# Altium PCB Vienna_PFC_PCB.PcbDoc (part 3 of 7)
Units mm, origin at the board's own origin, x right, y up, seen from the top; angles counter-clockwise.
Board outline 447.04 x 302.51 mm, 6 copper layers (Top Layer, Signal Layer 1, Signal Layer 2, Signal Layer 3, Signal Layer 4, Bottom Layer), stack 1.231 mm thick; 630 components, 255 nets, 1656 pads, 941 vias.
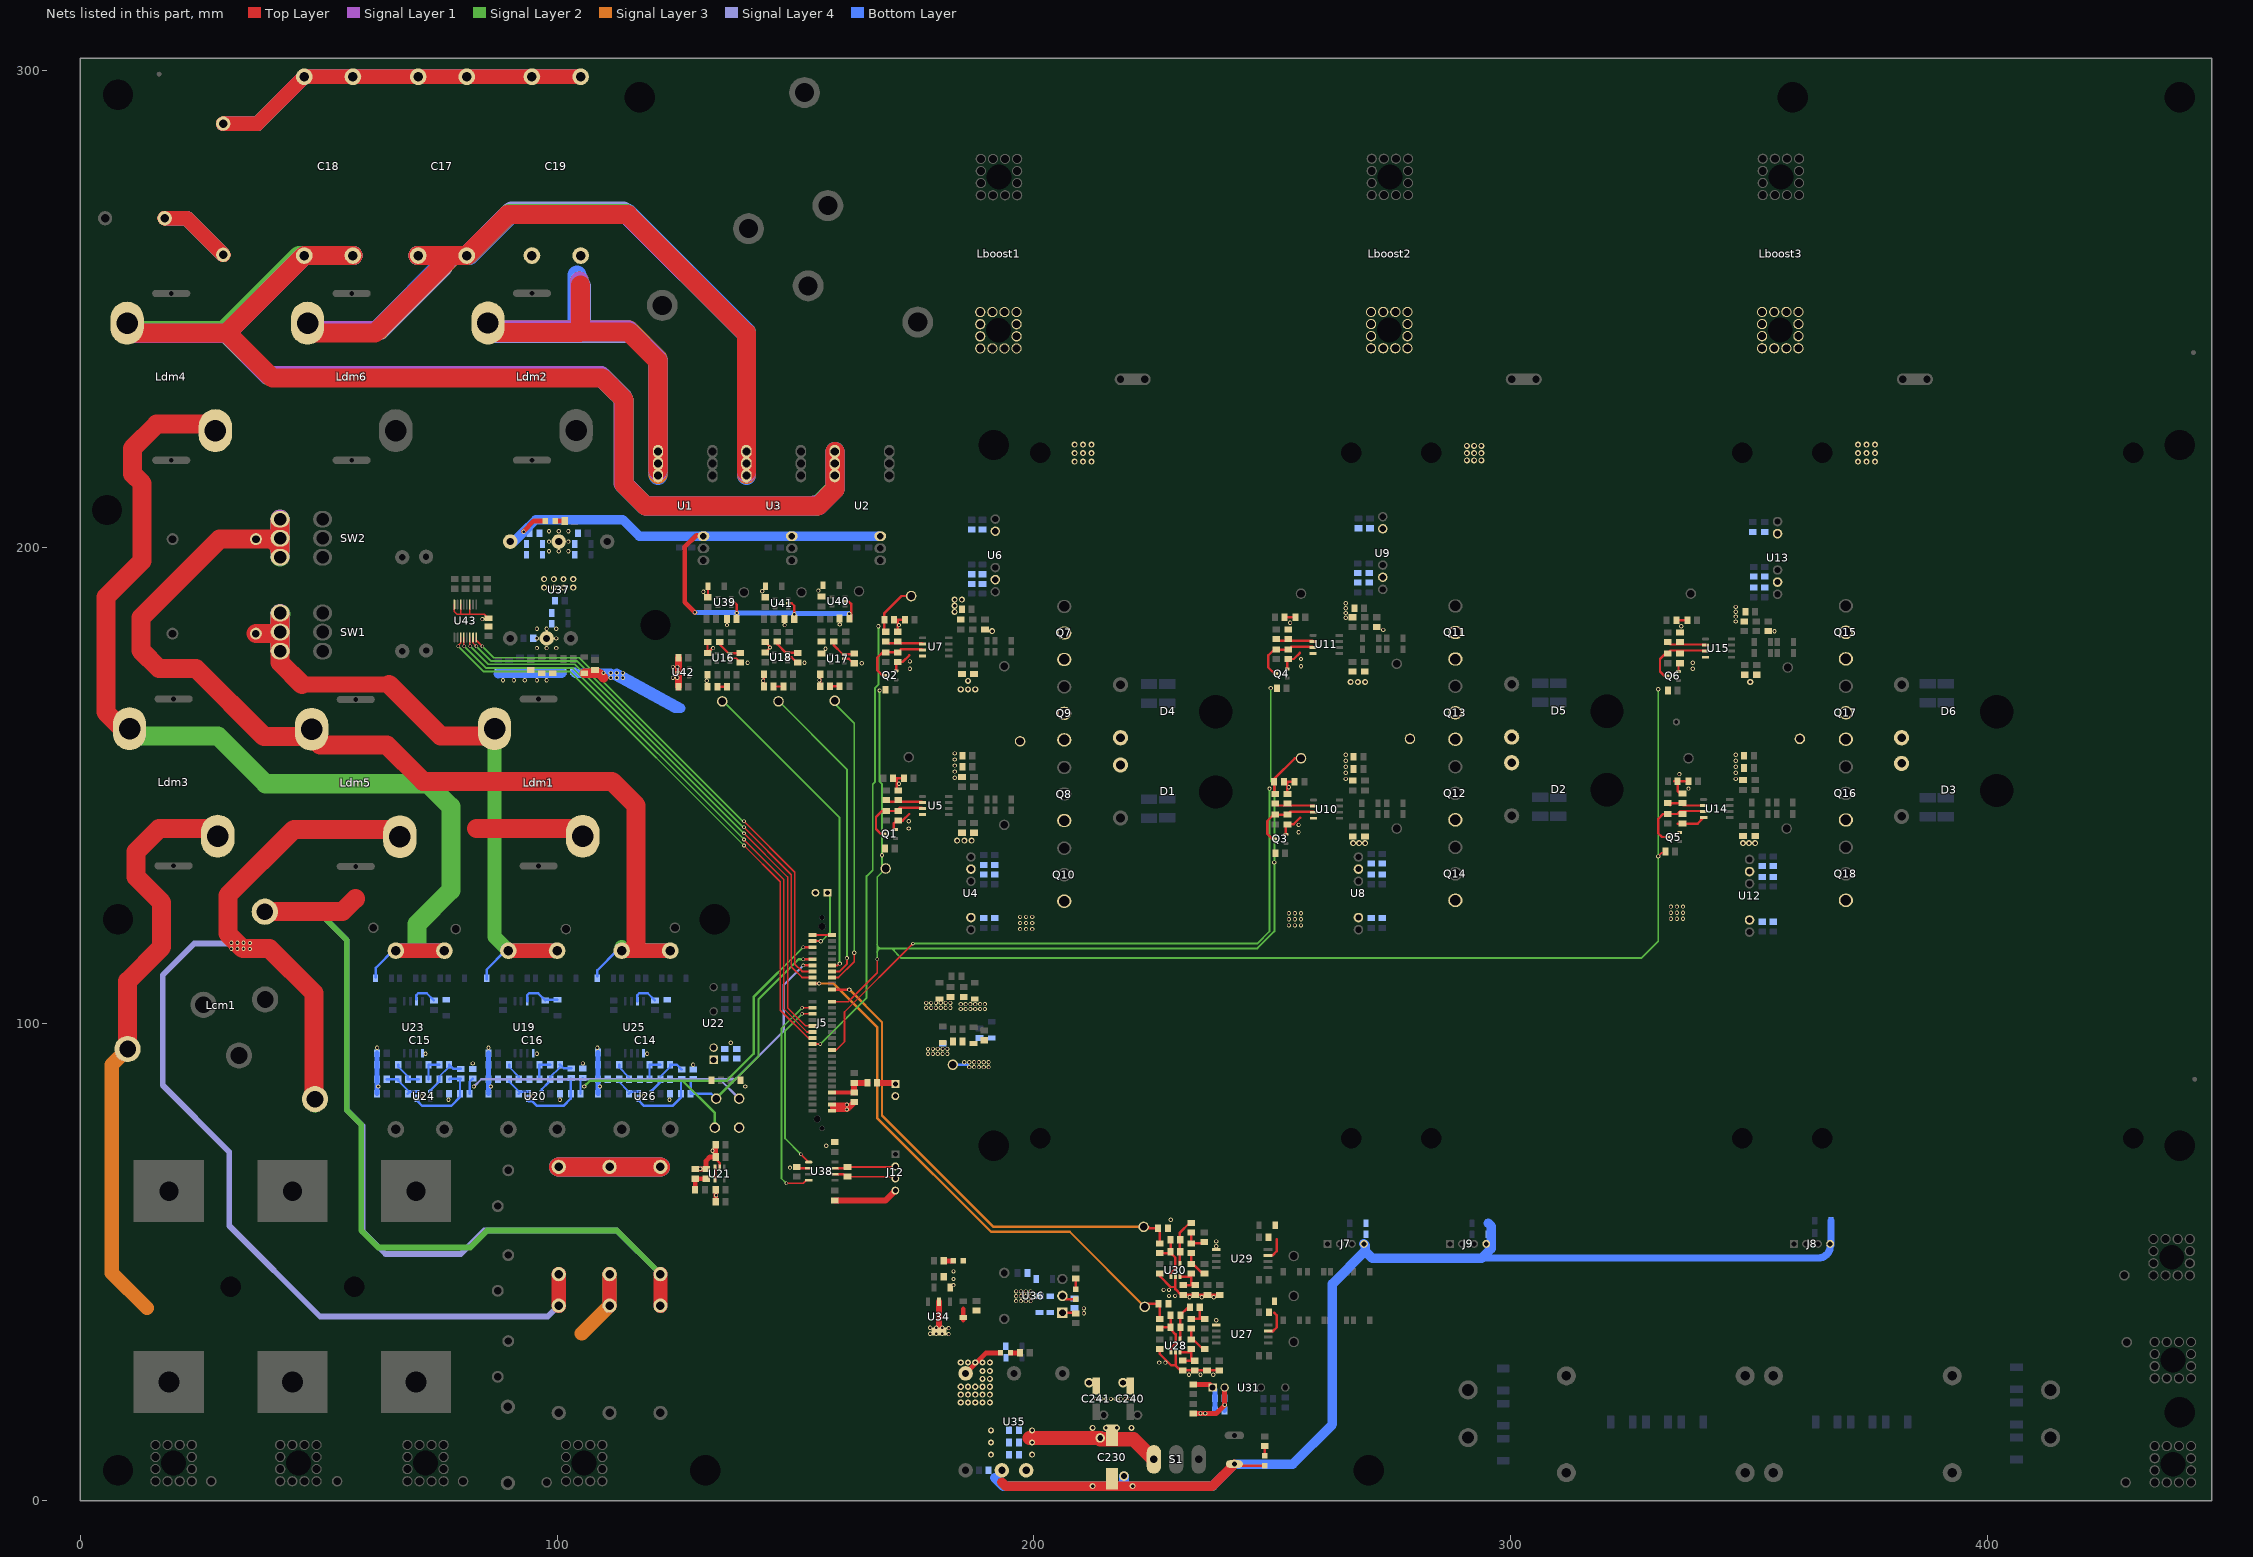
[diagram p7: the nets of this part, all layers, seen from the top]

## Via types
v1: diameter 1.27, hole 0.711, Top Layer to Bottom Layer, 487 vias
v2: diameter 0.889, hole 0.508, Top Layer to Bottom Layer, 425 vias
v3: diameter 0.762, hole 0.457, Top Layer to Bottom Layer, 28 vias
v4: diameter 0.889/0.889/0.889/0.889/0.889/0.889 (per signal layer), hole 0.508, Top Layer to Bottom Layer, 1 vias

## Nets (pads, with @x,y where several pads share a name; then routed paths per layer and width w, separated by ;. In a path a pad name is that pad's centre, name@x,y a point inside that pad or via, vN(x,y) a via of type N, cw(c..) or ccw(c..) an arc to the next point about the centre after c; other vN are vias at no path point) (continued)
-15V: C2.2 C3.2 C4.2 C5.2 C6.2 C7.2 C226.2 C228.2 C229.2 C245.1 C248.1 C251.1 D13.1 U1.9 U2.9 U3.9 U37.4 U39.2 U40.2 U41.2 | length 152.2
  Top Layer w0.508: U39.2@136.503,188.468 137.16,188.468 137.668,187.96 v2(137.668,186.182) 137.668,185.166 C245.1@137.414,184.912 ; U41.2@148.463,188.214 149.225,188.214 149.733,187.706 C251.1@149.733,184.912 ; U40.2@160.379,188.595 161.163,188.595 161.671,188.087 C248.1@161.671,185.039 ; C248.1@161.29,184.912 C248.1@161.671,184.912
  Top Layer w1: v2(92.964,203.2) 92.964,203.327 95.123,205.486 D13.1@97.502,205.486 ; v2(128.905,186.309) 126.746,188.468 126.746,200.114 129.159,202.438 130.531,202.438 U1.9@130.683,202.286
  Bottom Layer w1: v2(128.905,186.309) 137.541,186.309 v2(137.668,186.182) 149.479,186.182 v2(149.733,185.928) 149.86,186.055 v2(161.29,186.055)
  Bottom Layer w2: U37.4@90.17,201.168 90.932,201.168 v2(92.964,203.2) 95.504,205.74 113.792,205.74 117.246,202.286 U1.9@130.683,202.286 U3.9@148.717,202.286 ; U3.9@148.971,202.286 U3.9@149.225,202.286 U2.9@167.767,202.286
Button: C1.1 J5.54 R2.1 R3.2 | length 8.9
  Top Layer w0.762: J5.54@158.242,85.598 C1.1@162.306,85.598
  Top Layer w1.27: C1.1@162.306,85.598 R2.1@162.306,87.63 R3.2@165.1,87.63
CAN_H: J12.3 R55.2 U38.7 | length 12.8
  Top Layer w0.508: U38.7@158.261,69.723 160.655,69.723 R55.2@160.909,69.977 170.815,69.977 J12.3@170.942,70.104
CAN_L: J12.2 R55.1 U38.6 | length 13
  Top Layer w0.381: R55.1@160.528,67.945 R55.1@160.909,67.945 170.561,67.945 J12.2@170.942,67.564
  Top Layer w0.508: U38.6@158.261,68.453 160.02,68.453 R55.1@160.528,67.945
CAN_RX: J5.25 U38.4 | length 45.5
  Top Layer w0.381: v3(148.082,66.548) 151.638,66.548 U38.4@152.146,67.056 ; v3(151.384,103.378) J5.25@153.565,103.378
  Signal Layer 2 w0.381: v3(148.082,66.548) 147.066,67.564 147.066,99.06 v3(151.384,103.378)
CAN_TX: J5.27 U38.1 | length 36.8
  Top Layer w0.381: v3(151.13,72.644) U38.1@152.781,70.993 ; v3(151.384,102.108) J5.27@153.565,102.108
  Signal Layer 2 w0.381: v3(151.13,72.644) 147.828,75.946 147.828,98.552 v3(151.384,102.108)
DACOUT: J1.1 J5.3 | length 13.2
  Top Layer w0.381: J5.3@153.162,117.348 J5.3@153.565,117.348 v2(155.321,117.348)
  Signal Layer 2 w0.381: v2@155.448,117.348 157.226,119.126 157.226,126.282 ccw(c155.492,126.282) J1.1@156.718,127.508
DGND: C25.2 C26.2 C29.2 C30.2 C33.2 C36.2 C37.2 C38.2 C39.2 C40.2 C49.2 C50.2 C53.2 C54.2 C55.2 C56.2 C63.2 C64.2 C65.2 C66.2 C71.2 C72.2 C73.2 C74.2 C81.2 C82.2 C89.2 C90.2 C91.2 C92.2 C97.2 C98.2 C99.2 C100.2 C107.2 C108.2 Q1.2 Q2.2 Q3.2 Q4.2 Q5.2 Q6.2 R14.1 R16.1 R21.2 R31.1 R33.1 R47.1 R49.1 TP_DGND1.1 U4.2 U5.4 U6.2 U7.4 U8.2 U9.2 U10.4 U11.4 U12.2 U13.2 U14.4 U15.4 | length 54.1
  Top Layer w0.508: Q1.2@170.618,140.777 170.618,142.043 171.196,142.621 172.477,142.621 173.874,144.018 ; Q2.2@171.126,174.051 171.126,175.571 C50.2@171.45,175.895 172.477,175.895 173.874,177.292 ; C33.2@171.196,148.971 171.196,151.511 C25.2@172.72,151.511 ; C40.2@171.45,182.245 171.45,184.531 171.196,184.785 C26.2@172.974,184.785 ; R33.1@252.603,185.293 C66.2@254.889,185.293 ; Q3.2@252.865,139.761 252.865,141.535 C81.2@253.189,141.859 254.47,141.859 255.867,143.256 ; Q4.2@253.168,174.432 253.168,176.333 C82.2@253.365,176.53 254.519,176.53 255.789,177.8 ; C73.2@253.189,148.209 253.189,150.7 253.238,150.749 C65.2@254.713,150.749 ; 334.264,150.876 R47.1@335.153,150.876 ; R49.1@334.772,184.658 C92.2@337.058,184.658 ; 335.026,141.986 C107.2@336.042,141.986 339.217,141.986 U14.4@340.487,143.256 ; Q6.2@335.21,173.924 335.21,175.317 C108.2@335.534,175.641 ; C99.2@335.534,148.336 335.026,148.844 335.026,150.749 R47.1@335.153,150.876 ; 336.55,150.876 R47.1@335.153,150.876
  Bottom Layer w0.508: TP_DGND1.1@183.007,91.44 186.182,91.44
  other v2: 186.436,90.932 187.452,90.932 188.468,90.932 189.484,90.932 190.5,90.932 185.42,91.948 186.436,91.948 187.452,91.948 188.468,91.948 189.484,91.948 190.5,91.948 184.658,103.124 185.674,103.124 186.69,103.124 187.706,103.124 188.722,103.124 189.738,103.124 184.658,104.14 185.674,104.14 186.69,104.14 187.706,104.14 188.722,104.14 189.738,104.14 197.104,119.888 198.374,119.888 199.644,119.888 253.492,120.65 254.762,120.65 256.032,120.65 197.104,121.158 198.374,121.158 199.644,121.158 253.492,121.92 254.762,121.92 256.032,121.92 333.617,122.059 334.887,122.059 336.157,122.059 197.104,122.428 198.374,122.428 199.644,122.428 253.492,123.19 254.762,123.19 256.032,123.19 333.617,123.329 334.887,123.329 336.157,123.329 333.617,124.599 334.887,124.599 336.157,124.599 255.524,140.208 173.736,140.97 255.524,141.732 173.736,142.494 337.312,149.352 253.492,149.606 171.704,150.368 335.407,152.4 173.99,174.498 338.201,174.498 256.032,175.006 338.201,175.768 173.99,176.022 256.032,176.53 335.788,183.388 171.704,183.642 253.746,184.15
DGND2: C192.2 C193.2 C194.2 C195.2 C196.2 C197.2 C258.2 C259.2 C260.2 C261.2 C262.2 R162.2 U43.11 U43.14 U43.16 | length 29
  Top Layer w0.33: U43.16@78.456,187.96 78.456,186.466 78.994,185.928 80.01,185.928 ; U43.14@79.756,187.96 79.756,186.182 80.01,185.928 ; U43.11@81.706,187.96 81.706,186.088 81.866,185.928 ; C262.2@85.598,185.068 84.738,185.928 81.866,185.928 ; 80.01,185.928 81.866,185.928
  Bottom Layer w2: 89.928,173.523 88.621,173.5 87.644,173.482 87.63,173.482 87.643,173.482 88.622,173.499 89.928,173.521 C195.2@92.202,173.56 C194.2@94.488,173.56 C193.2@96.774,173.56 C192.2@99.06,173.56 R162.2@100.916,173.56
  other v2: 88.646,172.085 90.932,172.085 93.218,172.085 95.758,172.085 97.79,172.085 84.328,184.912
EN_PWM: J5.24 R19.1 R20.1 R36.1 R37.1 R52.1 R53.1 TP_EN1.1 | length 428.7
  Top Layer w0.381: J5.24@157.625,104.648 161.036,104.648 167.132,110.744 v3(167.132,113.538) ; v2(330.962,135.128) 331.724,135.89
  Signal Layer 2 w0.254: 170.756,115.346 cw(c170.95,115.51) 171.016,115.755
  Signal Layer 2 w0.381: v3(167.132,113.538) 167.132,115.57 167.132,130.81 TP_EN1.1@168.91,132.588 168.148,133.35 v2(168.148,135.382) 168.148,140.657 168.161,140.67 168.161,150.286 167.64,150.807 v2(167.64,169.926) ; 167.259,115.824 170.307,115.824 ; v2(249.682,170.434) 249.682,150.876 250.444,150.114 v2(250.444,133.858) 250.444,119.39 246.878,115.824 170.18,115.824 170.307,115.697 172.212,113.792 327.406,113.792 330.962,117.348 v2(330.962,135.128) v2(330.962,170.18)
  Signal Layer 2 w0.4: 167.132,115.062 cw(c167.894,115.062) 167.894,115.824 cw(c167.894,116.586) 167.132,116.586
GND: C1.2 C34.2 C35.2 C51.2 C52.2 C109.2 C110.2 C111.2 C112.2 C113.2 C114.2 C117.1 C118.1 C119.2 C121.2 C122.1 C123.2 C124.2 C125.2 C127.2 C128.2 C129.2 C132.1 C133.1 C134.2 C135.2 C139.1 C140.2 C142.2 C145.1 C146.1 C147.2 C149.1 C150.2 C152.2 C155.1 C156.1 C157.2 C159.1 C160.2 C164.1 C165.1 C166.2 C168.1 C169.2 C171.2 C190.2 C191.2 C198.2 C209.2 C210.2 C211.2 C212.2 C213.2 C214.2 C215.2 C216.2 C217.2 C218.2 C219.2 C220.2 C221.2 C222.2 C223.2 C224.2 C225.2 C226.1 C227.2 C228.1 C229.1 C231.2 C238.2 C239.2 C240.2 C241.2 C242.1 C243.2 C244.2 C245.2 C246.2 C247.2 C248.2 C249.2 C250.2 C251.2 C252.2 C253.2 C256.2 C257.2 D10.1 D11.1 D12.1 J1.2 J4.2 J5.1 J5.2 J5.58 J5.60 J12.1 R21.1 R57.1 R59.1 R63.1 R65.1 R69.1 R71.1 R119.1 R131.1 R162.1 R167.1 R170.2 R171.1 R174.1 R177.1 R178.2 TP_GND.1 U16.2 U17.2 U18.2 U19.5 U20.2 U21.2 U22.2 U23.5 U24.2 U25.5 U26.2 U27.5 U28.2 U29.5 U30.2 U31.2 U34.2 U34.4 U35.4 U36.2 U37.2 U37.5 U38.2 U42.3 | length 207.9
  Top Layer w0.381: C109.2@131.572,177.8 R57.1@131.572,180.086 ; C243.2@131.572,189.484 131.65,189.562 R171.1@131.65,191.77 ; U16.2@136.249,176.784 136.249,176.669 137.529,176.669 C244.2@138.43,175.768 ; J5.1@153.565,118.618 J5.2@157.625,118.618
  Top Layer w0.508: C109.2@131.572,177.8 132.588,178.816 v2(132.715,178.816) v2@132.842,178.816 ; C127.2@133.274,72.078 133.274,71.628 134.102,70.8 U21.2@134.102,69.952 ; C114.2@143.383,170.766 R71.1@143.383,173.306 ; C111.2@143.637,177.878 144.653,178.894 v2(144.653,178.943) 144.653,179.099 R69.1@143.637,180.115 ; U18.2@148.314,176.862 149.207,176.862 150.301,175.768 C250.2@150.495,175.768 ; C242.1@150.495,69.723 U38.2@152.781,69.723 ; C112.2@155.194,170.815 R65.1@155.194,173.355 ; U17.2@160.23,176.591 161.162,176.591 162.112,175.641 C247.2@162.306,175.641 ; U36.2@205.994,42.926 206.663,42.257 D11.1@208.788,42.257 ; C166.2@226.39,47.6 226.39,47.092 228.676,44.806 229.692,44.806 ; C157.2@226.416,31.752 226.416,30.759 228.829,28.346 229.718,28.346 ; U30.2@229.692,46.987 229.692,44.806 ; U28.2@229.718,31.139 229.718,28.346 ; R131.1@231.343,43.155 R131.1@231.133,43.155 ; C156.1@238.862,27.303 C155.1@236.322,27.303 236.317,27.307 C160.2@233.782,27.307 230.757,27.307 229.718,28.346 ; C165.1@238.963,43.155 C164.1@236.423,43.155 C169.2@233.883,43.155 R131.1@231.133,43.155 ; 229.692,44.806 229.692,44.348 230.886,43.155 R131.1@231.133,43.155
  Top Layer w1.016: C123.2@128.956,69.538 C124.2@131.242,69.538 131.242,71.298 132.022,72.078 C127.2@133.274,72.078 C128.2@133.274,74.618 ; C220.2@133.274,62.68 C121.2@133.274,65.22 ; 185.2,37.846 C215.2@185.2,38.432 185.2,40.2 ; U35.4@185.674,26.67 189.992,30.988 D10.1@193.006,30.988 ; C171.2@233.401,18.263 238.227,18.263 240.005,20.041 U31.2@240.005,23.82
  Top Layer w1.27: C198.2@158.242,62.992 168.91,62.992 J12.1@170.942,65.024 ; 158.242,82.515 J5.58@158.242,82.804 ; 160.782,82.515 161.255,82.515 C1.2@162.306,83.566 ; U34.4@180.086,35.483 U34.2@180.086,41.733
  Top Layer w1.5: C252.2@125.476,170.688 125.476,173.92 C253.2@125.476,176.784
  Top Layer w2: C256.2@105.664,173.56 108.761,173.56 109.728,172.593 ; 158.242,82.515 160.782,82.515
  Bottom Layer w1.016: C142.2@62.23,85.344 C140.2@62.23,88.392 C133.1@62.23,91.44 C132.1@62.23,93.853 ; C129.2@85.598,85.852 C117.1@85.598,91.44 C118.1@85.598,93.853 ; C152.2@108.585,85.344 C145.1@108.585,91.44 C146.1@108.585,93.98 ; C238.2@240.005,18.898 C239.2@240.005,21.438 U31.2@240.005,23.82
  Bottom Layer w2: R162.1@103.759,173.56 C190.2@105.664,173.56 C191.2@107.95,173.56 109.722,173.571 109.728,173.571 109.933,173.573 111.246,173.581 111.667,173.351 112.216,173.05 112.644,172.816 113.194,172.516 113.622,172.282 124.714,166.215 125.978,166.223 113.919,172.825 113.491,173.059 112.942,173.36 v2@112.522,173.589
  other v1: 184.658,20.574 186.182,20.574 187.706,20.574 189.23,20.574 190.754,20.574 184.658,22.225 186.182,22.225 187.706,22.225 189.23,22.225 190.754,22.225 184.658,23.876 186.182,23.876 187.706,23.876 189.23,23.876 190.754,23.876 189.23,25.527 190.754,25.527 189.23,27.178 190.754,27.178 184.658,28.956 186.182,28.956 187.706,28.956 189.23,28.956 190.754,28.956 97.282,191.516 99.314,191.516 101.346,191.516 103.378,191.516 97.282,193.294 99.314,193.294 101.346,193.294 103.378,193.294
  other v2: 234.95,18.288 235.966,18.288 240.03,20.066 213.106,21.336 214.122,21.336 215.138,21.336 216.154,21.336 217.17,21.336 218.186,21.336 219.202,21.336 220.218,21.336 232.537,26.416 234.95,26.416 237.617,26.416 226.314,28.956 227.584,28.956 182.118,34.925 178.232,34.987 179.502,34.987 180.772,34.987 182.118,36.195 178.232,36.257 179.502,36.257 180.772,36.257 238.252,37.846 196.266,41.845 197.282,41.845 198.298,41.845 199.314,41.845 232.664,42.672 235.204,42.672 237.744,42.672 196.266,42.861 197.282,42.861 198.298,42.861 199.314,42.861 228.346,42.926 229.616,42.926 196.266,43.877 197.282,43.877 198.298,43.877 199.314,43.877 227.203,44.196 228.346,44.196 183.134,45.212 183.134,46.482 183.134,48.068 238.252,53.34 238.252,54.356 228.727,58.928 133.35,64.008 130.048,69.596 148.844,69.85 132.588,73.406 156.464,74.422 160.782,82.042 160.782,83.058 77.216,84.074 100.584,84.074 123.571,84.074 71.628,84.836 94.996,84.836 118.11,84.836 62.484,86.868 86.106,86.868 108.966,86.868 139.446,86.868 128.524,91.44 82.296,91.694 105.41,91.694 72.39,93.726 95.758,93.726 118.872,93.726 177.8,93.726 178.816,93.726 179.832,93.726 180.848,93.726 181.864,93.726 177.8,94.742 178.816,94.742 179.832,94.742 180.848,94.742 181.864,94.742 62.23,94.996 85.598,94.996 108.458,94.996 136.398,96.012 177.419,103.378 178.435,103.378 179.451,103.378 180.467,103.378 181.483,103.378 182.499,103.378 177.419,104.394 178.435,104.394 179.451,104.394 180.467,104.394 181.483,104.394 182.499,104.394 131.396,171.958 143.207,171.958 155.018,172.085 111.252,172.593 112.522,172.593 113.792,172.593 124.284,172.593 125.173,172.593 109.728,173.609 111.252,173.609 112.522,173.609 113.792,173.609 124.284,174.879 125.222,174.879 163.908,175.641 139.954,175.768 151.892,175.768 156.288,178.689 95.758,178.816 97.79,178.816 99.822,178.816 95.758,180.848 99.822,180.848 95.758,182.88 97.79,182.88 99.822,182.88 135.636,183.642 147.701,183.642 159.258,183.769 130.683,190.627 143.002,190.754 154.813,190.881 98.298,199.136 100.33,199.136 102.362,199.136 98.298,201.168 102.362,201.168 98.298,203.327 100.33,203.327 102.362,203.327
GND1: C21.2 C22.2 C23.2 C24.2 C27.2 C28.2 C31.2 C32.2 C41.1 C42.1 C43.1 C44.1 C45.2 C46.2 C47.2 C48.2 Q7.3 Q8.3 Q9.3 Q10.3 R8.1 R10.1 TP_GND1.1 U4.6 U6.6
  other v1: 183.896,138.43 185.42,138.43 186.944,138.43 184.658,170.18 186.182,170.18 187.706,170.18 186.182,171.958 191.262,182.372 183.388,186.436 183.388,187.706 183.388,188.976 184.912,188.976
  other v2: 183.388,151.638 183.388,152.908 183.388,154.178 183.388,155.448 183.388,156.718
GND3: C57.2 C58.2 C59.2 C60.2 C61.2 C62.2 C67.1 C68.1 C69.2 C70.2 C75.1 C76.1 C77.2 C78.2 C79.2 C80.2 Q11.3 Q12.3 Q13.3 Q14.3 R25.1 R27.1 TP_GND2.1 U8.6 U9.6
  other v1: 266.954,137.922 268.224,137.922 269.494,137.922 266.446,171.704 267.97,171.704 269.494,171.704
  other v2: 265.43,151.384 265.43,152.654 265.43,153.924 265.43,155.194 265.43,156.464 273.304,182.626 265.43,185.166 265.43,186.182 265.43,187.198 265.43,188.214
GND5: C83.2 C84.2 C85.2 C86.2 C87.2 C88.2 C93.1 C94.1 C95.2 C96.2 C101.1 C102.1 C103.2 C104.2 C105.2 C106.2 Q15.3 Q16.3 Q17.3 Q18.3 R41.1 R43.1 TP_GND3.1 U12.6 U13.6
  other v1: 348.742,137.922 350.012,137.922 351.282,137.922 350.266,171.704
  other v2: 347.218,151.384 347.218,152.654 347.218,153.924 347.218,155.194 347.218,156.464 355.346,182.372 347.218,184.404 347.218,185.42 347.218,186.436 347.218,187.452
GND_IN: C206.2 C207.2 C208.2 C230.2 C232.2 C233.2 C234.2 C235.2 C236.2 C237.2 D9.1 J6.2 J7.1 J8.1 J9.1 R168.2 U35.2 | length 290.7
  Top Layer w0.508: J6.2@242.062,7.668 242.398,7.332 D9.1@248.412,7.332
  Top Layer w2: 193.294,3.81 194.056,3.048 v1(212.344,3.048) v1(220.726,3.048) 237.442,3.048 J6.2@242.062,7.668
  Bottom Layer w1.524: 293.941,50.863 364.517,50.863 ccw(c364.517,53.403) 366.313,51.607 ccw(c364.582,53.338) 367.03,53.338 367.206,53.514 C234.2@367.206,56.134 C235.2@367.206,58.674
  Bottom Layer w2: 191.77,4.826 193.548,3.048 v1(212.344,3.048) 218.948,3.048 ; C230.2@218.908,5.144 218.908,3.088 218.948,3.048 ; J7.1@269.24,53.848 269.494,53.594 269.494,52.331 ; C233.2@295.324,58.166 295.91,57.58 295.91,52.832 293.941,50.863 270.962,50.863 269.494,52.331 ; 218.948,3.048 v1(220.726,3.048) 237.49,3.048 242.062,7.62 J6.2@242.062,7.668 254.302,7.668 262.636,16.002 262.636,45.473 269.494,52.331
  other v1: 191.008,9.652 191.008,12.192 191.008,14.732
NetC8_2: C8.2 C11.2 Lcm1.4 Ldm5.1 | length 291.1
  Top Layer w3: C8.2@100.33,40.894 C11.2@100.33,47.498
  Top Layer w4: Lcm1.4@49.222,84.207 49.022,84.408 49.022,106.426 39.674,115.774 34.086,115.774 30.938,118.922 30.938,126.95 44.762,140.774 Ldm5.1@67.014,140.774
  Signal Layer 1 w1.2: C8.2@100.33,40.894 C11.2@100.33,47.498
  Signal Layer 2 w1.2: C8.2@100.33,40.894 C11.2@100.33,47.498
  Signal Layer 2 w4: Lcm1.4@49.222,83.366 Lcm1.4@49.222,84.207
  Signal Layer 3 w1.2: C8.2@100.33,40.894 C11.2@100.33,47.498
  Signal Layer 4 w1.2: v2@33.274,116.84 23.876,116.84 17.272,110.236 17.272,87.122 31.242,73.152 31.242,57.658 50.292,38.608 98.044,38.608 C8.2@100.33,40.894 C11.2@100.33,47.498 C11.2@100.33,47.752
  Bottom Layer w1.2: C8.2@100.33,40.894 C11.2@100.33,47.498
  other v2: 35.56,115.697 31.674,115.759 32.944,115.759 34.214,115.759 35.56,116.967 31.674,117.029 32.944,117.029 34.214,117.029
NetC9_2: C9.2 C12.2 Lcm1.6 Ldm3.1 | length 164.1
  Top Layer w3: C9.2@110.998,40.894 C12.2@110.998,47.498
  Top Layer w4: Lcm1.6@9.906,94.742 9.906,108.966 17.018,116.078 17.018,125.476 11.684,130.81 11.684,136.144 16.51,140.97 Ldm3.1@27.178,140.97
  Signal Layer 1 w1.2: C9.2@110.998,40.894 C12.2@110.998,47.498
  Signal Layer 2 w1.2: C9.2@110.998,40.894 C12.2@110.998,47.498
  Signal Layer 3 w3: Lcm1.6@9.906,94.742 6.604,91.44 6.604,47.752 13.97,40.386 ; 105.156,35.052 C9.2@110.998,40.894 C12.2@110.998,47.498
  Bottom Layer w1.2: C9.2@110.998,40.894 C12.2@110.998,47.498
NetC10_2: C10.2 C13.2 Lcm1.2 Ldm1.1 | length 386.6
  Top Layer w3: C10.2@121.666,40.894 C13.2@121.666,47.498
  Top Layer w4: Lcm1.2@38.688,123.524 54.944,123.524 57.667,126.247 ; 83.058,140.97 Ldm1.1@105.918,140.97
  Signal Layer 1 w1.2: C10.2@121.666,40.894 C13.2@121.666,47.498
  Signal Layer 2 w1.2: Lcm1.2@38.688,123.524 49.958,123.524 55.88,117.602 55.88,81.941 58.9,78.921 58.9,56.67 62.484,53.086 81.788,53.086 85.344,56.642 112.522,56.642 C13.2@121.666,47.498 C10.2@121.666,40.894
  Signal Layer 3 w1.2: C10.2@121.666,40.894 C13.2@121.666,47.498
  Signal Layer 4 w1.2: Lcm1.2@38.688,123.524 49.958,123.524 55.88,117.602 55.88,81.941 59.182,78.639 59.182,56.541 64.017,51.706 79.765,51.706 84.701,56.642 112.522,56.642 C13.2@121.666,47.498 C10.2@121.666,40.894 C10.2@121.666,40.64
  Bottom Layer w1.2: C10.2@121.666,40.894 C13.2@121.666,47.498
NetC11_1: C11.1 C12.1 C13.1 | length 85.3
  Top Layer w4: C11.1@100.33,69.998 C12.1@110.998,69.998 C13.1@121.666,69.998
  Signal Layer 1 w4: C11.1@100.33,69.998 C12.1@110.998,69.998 C13.1@121.666,69.998
  Signal Layer 2 w4: C11.1@100.33,69.998 C12.1@110.998,69.998 C13.1@121.666,69.998
  Bottom Layer w4: C11.1@100.33,69.998 C12.1@110.998,69.998 C13.1@121.666,69.998
NetC14_2: C14.2 Ldm5.2 R96.2 Rsurge2.1 SW2.4 | length 284.9
  Top Layer w3: 38.1,201.676 38.367,201.943 39.337,201.943 39.604,201.676 SW2.4@41.9,199.38 ; C14.2@113.538,115.351 C14.2@123.738,115.351
  Top Layer w4: 39.604,201.676 38.1,201.676 Rsurge2.1@36.83,201.676 29.185,201.676 12.7,185.191 12.7,178.308 16.51,174.498 24.281,174.498 38.505,160.274 48.514,160.274 50.292,158.496 64.262,158.496 71.882,150.876 93.218,150.876 ; SW2.4@41.9,199.38 SW2.4@41.9,201.866 SW2.4@41.9,205.486 ; 92.456,150.876 93.218,150.876 ; 116.586,116.332 116.586,145.796 111.506,150.876 93.218,150.876
  Signal Layer 1 w3: C14.2@113.538,115.351 C14.2@123.738,115.351
  Signal Layer 1 w4: SW2.4@41.9,198.116 SW2.4@41.9,201.866 SW2.4@41.9,205.866
  Signal Layer 2 w3: C14.2@113.538,116.078 C14.2@113.538,115.351 C14.2@123.738,115.351
  Signal Layer 2 w4: SW2.4@41.9,197.932 SW2.4@41.9,201.866 SW2.4@41.9,205.866
  Signal Layer 3 w3: C14.2@113.538,115.351 C14.2@123.738,115.351
  Signal Layer 4 w3: C14.2@113.538,115.351 C14.2@123.738,115.351
  Bottom Layer w0.508: R96.2@108.458,109.982 108.458,111.252 112.557,115.351 C14.2@113.538,115.351 C14.2@123.738,115.351
NetC15_2: C15.2 Ldm3.2 Ldm4.1 R84.2 | length 248.1
  Top Layer w3: C15.2@66.167,115.351 C15.2@76.367,115.351
  Top Layer w4: Ldm3.2@10.308,160.398 5.334,165.372 5.334,189.484 12.954,197.104 12.954,213.36 10.922,215.392 10.922,220.726 16.002,225.806 Ldm4.1@26.67,225.806
  Signal Layer 1 w3: C15.2@66.167,115.351 C15.2@76.367,115.351
  Signal Layer 2 w3: C15.2@66.167,115.351 C15.2@76.367,115.351
  Signal Layer 2 w4: Ldm3.2@10.308,160.398 28.832,160.398 38.862,150.368 72.898,150.368 77.724,145.542 77.724,128.016 70.612,120.904 70.612,117.094
  Signal Layer 4 w3: C15.2@66.167,115.351 C15.2@76.367,115.351
  Bottom Layer w0.508: R84.2@61.976,109.728 61.976,111.76 65.913,115.697 C15.2@66.167,115.697 ; C15.2@66.167,115.351 C15.2@76.367,115.351
NetC16_2: C16.2 Ldm1.2 R72.2 Rsurge1.1 SW1.4 | length 187.8
  Top Layer w3: C16.2@89.789,115.351 C16.2@99.989,115.351
  Top Layer w3.302: 46.482,171.196 64.77,171.196
  Top Layer w4: Rsurge1.1@36.817,181.864 41.592,181.864 SW1.4@41.91,182.182 ; SW1.4@41.91,185.674 SW1.4@41.91,182.182 ; 46.482,171.196 41.91,175.768 SW1.4@41.91,178.182 SW1.4@41.91,182.182 ; 64.77,171.196 75.59,160.376 Ldm1.2@86.868,160.376
  Signal Layer 1 w3: C16.2@89.789,115.351 C16.2@99.989,115.351
  Signal Layer 1 w4: SW1.4@41.91,178.182 SW1.4@41.91,182.182 SW1.4@41.91,186.116
  Signal Layer 2 w3: Ldm1.2@86.868,160.376 86.868,118.272 C16.2@89.789,115.351 C16.2@99.989,115.351
  Signal Layer 2 w4: SW1.4@41.91,178.182 SW1.4@41.91,182.182 41.91,185.932 SW1.4@42.056,185.932
  Signal Layer 3 w3: C16.2@89.789,115.351 C16.2@99.989,115.351
  Bottom Layer w0.508: R72.2@85.246,109.347 R72.2@85.246,109.601 85.246,111.408 89.189,115.351 C16.2@89.789,115.351 C16.2@99.989,115.351
NetC17_1: C17.1 C18.1 C19.1 C20.2 | length 474.1
  Top Layer w3: C20.2@29.972,288.832 37.144,288.832 C18.1@46.97,298.658 C18.1@57.17,298.658 C17.1@70.846,298.658 C17.1@81.046,298.658 C19.1@94.722,298.658 C19.1@104.922,298.658
  Signal Layer 1 w3: C20.2@29.972,288.832 37.144,288.832 C18.1@46.97,298.658 C18.1@57.17,298.658 C17.1@70.846,298.658 C17.1@81.046,298.658 C19.1@94.722,298.658 C19.1@104.922,298.658
  Signal Layer 2 w3: C20.2@29.972,288.832 37.144,288.832 C18.1@46.97,298.658 C18.1@57.17,298.658 C17.1@70.846,298.658 C17.1@81.046,298.658 C19.1@94.722,298.658 C19.1@104.922,298.658
  Signal Layer 3 w3: C20.2@29.972,288.832 37.144,288.832 C18.1@46.97,298.658 C18.1@57.17,298.658 C17.1@70.846,298.658 C17.1@81.046,298.658 C19.1@94.722,298.658 C19.1@104.922,298.658
  Signal Layer 4 w3: C20.2@29.972,288.832 37.118,288.832 46.944,298.658 C18.1@46.97,298.658 C18.1@57.17,298.658 C17.1@70.846,298.658 C17.1@81.046,298.658 C19.1@94.722,298.658 C19.1@104.922,298.658
  Bottom Layer w3: C20.2@29.972,288.832 37.144,288.832 C18.1@46.97,298.658 C18.1@57.17,298.658 C17.1@70.846,298.658 C17.1@81.046,298.658 C19.1@94.722,298.658 C19.1@104.922,298.658
NetC17_2: C17.2 Ldm6.2 U3.1 U3.2 U3.3 | length 895.1
  Top Layer w4: Ldm6.2@47.646,244.954 61.82,244.954 76.708,259.842 75.392,261.158 ; C17.2@70.846,261.158 75.392,261.158 ; U3.1@139.7,215.9 U3.2@139.7,217.526 U3.3@139.7,220.066 139.7,244.856 114.808,269.748 89.636,269.748 C17.2@81.046,261.158 75.392,261.158
  Signal Layer 1 w4: Ldm6.2@47.646,245.462 62.328,245.462 77.216,260.35 77.216,261.158 ; C17.2@70.846,261.158 77.216,261.158 ; U3.1@139.7,215.586 U3.2@139.7,217.526 U3.3@139.7,220.066 139.7,244.727 114.653,269.774 89.662,269.774 C17.2@81.046,261.158 77.216,261.158
  Signal Layer 2 w4: Ldm6.2@47.646,245.462 62.328,245.462 76.962,260.096 75.9,261.158 ; C17.2@70.846,261.158 75.9,261.158 ; U3.1@139.7,215.84 U3.2@139.7,217.526 U3.3@139.7,220.066 139.7,244.856 114.554,270.002 89.916,270.002 81.072,261.158 C17.2@81.046,261.158 75.9,261.158
  Signal Layer 3 w4: Ldm6.2@47.646,245.462 62.582,245.462 77.724,260.604 77.17,261.158 ; C17.2@70.846,261.158 77.17,261.158 ; U3.1@139.7,215.284 U3.2@139.7,217.526 U3.3@139.7,220.066 139.7,244.856 114.808,269.748 89.916,269.748 81.326,261.158 C17.2@81.046,261.158 77.17,261.158
  Signal Layer 4 w4: Ldm6.2@47.646,245.462 62.836,245.462 76.2,258.826 73.868,261.158 ; C17.2@70.846,261.158 73.868,261.158 ; U3.1@139.7,215.586 U3.2@139.7,217.526 U3.3@139.7,220.066 139.7,244.727 113.917,270.51 90.398,270.51 C17.2@81.046,261.158 73.868,261.158
  Bottom Layer w4: Ldm6.2@47.646,245.462 62.132,245.462 77.828,261.158 ; C17.2@70.846,261.158 77.828,261.158 ; U3.1@139.7,214.986 U3.2@139.7,217.526 U3.3@139.7,220.066 139.7,245.11 114.808,270.002 90.424,270.002 81.58,261.158 C17.2@81.046,261.158 77.828,261.158
NetC18_2: C18.2 Ldm4.2 U2.1 U2.2 U2.3 | length 975.6
  Top Layer w4: Ldm4.2@9.8,244.954 30.766,244.954 ; C18.2@57.17,261.158 C18.2@46.97,261.158 30.766,244.954 ; U2.3@158.242,220.066 U2.2@158.242,217.526 U2.1@158.242,214.986 158.242,212.09 154.738,208.586 118.566,208.586 114.046,213.106 114.046,230.886 111.242,233.69 111.242,233.738 111.194,233.738 109.444,235.488 100.471,235.488 100.441,235.458 69.671,235.458 69.667,235.462 40.258,235.462 30.766,244.954
  Signal Layer 1 w4: Ldm4.2@9.8,245.462 10.406,244.856 30.668,244.856 ; C18.2@57.17,261.158 C18.2@46.97,261.158 30.668,244.856 ; U2.3@158.242,220.066 U2.2@158.242,217.526 U2.1@158.242,214.986 158.242,212.09 154.94,208.788 153.859,208.788 153.657,208.586 118.566,208.586 113.792,213.36 113.792,231.394 109.224,235.962 39.562,235.962 30.668,244.856
  Signal Layer 2 w4: Ldm4.2@9.8,245.462 30.128,245.462 ; C18.2@57.17,261.158 C18.2@46.97,261.158 45.824,261.158 30.128,245.462 ; U2.3@158.242,220.066 U2.2@158.242,217.526 U2.1@158.242,214.986 158.242,212.344 154.686,208.788 153.859,208.788 153.657,208.586 118.631,208.586 113.792,213.425 113.792,231.394 109.474,235.712 39.878,235.712 30.128,245.462
  Signal Layer 3 w4: Ldm4.2@9.8,245.462 30.832,245.462 46.528,261.158 C18.2@46.97,261.158 C18.2@57.17,261.158
  Signal Layer 4 w4: Ldm4.2@9.8,245.462 29.874,245.462 ; C18.2@57.17,261.158 C18.2@46.97,261.158 31.274,245.462 29.874,245.462 ; U2.3@158.242,220.066 U2.2@158.242,217.526 U2.1@158.242,214.986 158.242,212.193 154.634,208.586 118.631,208.586 114.046,213.171 114.046,230.886 111.242,233.69 111.242,233.738 111.194,233.738 108.966,235.966 51.171,235.966 51.167,235.962 39.374,235.962 29.874,245.462
  Bottom Layer w4: Ldm4.2@9.8,245.462 31.274,245.462 C18.2@46.97,261.158 C18.2@57.17,261.158
NetC19_2: C19.2 Ldm2.2 U1.1 U1.2 U1.3 | length 432.9
  Top Layer w4: Ldm2.2@85.492,244.98 104.792,244.98 104.922,245.11 ; 104.922,254.996 104.922,245.11 ; U1.1@121.158,216.154 U1.2@121.158,217.526 U1.3@121.158,220.066 121.158,239.014 115.062,245.11 104.922,245.11
  Signal Layer 1 w4: Ldm2.2@85.492,245.488 104.394,245.488 ; 104.648,255.824 104.648,245.742 104.394,245.488 ; U1.1@121.158,215.893 U1.2@121.158,217.526 U1.3@121.158,220.066 121.158,239.268 114.938,245.488 104.394,245.488
  Signal Layer 2 w4: Ldm2.2@85.492,245.488 104.648,245.488 ; 104.648,255.778 104.648,245.488 ; U1.1@121.158,215.958 U1.2@121.158,217.526 U1.3@121.158,220.066 121.158,239.268 114.938,245.488 104.648,245.488
  Signal Layer 3 w4: Ldm2.2@85.492,245.488 103.632,245.488 ; 104.648,255.062 104.648,246.504 103.632,245.488 ; U1.1@121.158,215.284 U1.2@121.158,217.526 U1.3@121.158,220.066 121.158,239.522 115.192,245.488 103.632,245.488
  Signal Layer 4 w4: Ldm2.2@85.492,245.488 86.124,244.856 105.156,244.856 ; 105.156,254.808 105.156,244.856 ; U1.1@121.158,215.958 U1.2@121.158,217.526 U1.3@121.158,220.066 121.158,239.268 115.57,244.856 105.156,244.856
  Bottom Layer w4: Ldm2.2@85.492,245.488 104.14,245.488 ; 104.14,257.094 104.14,245.488 ; U1.1@121.158,214.986 U1.2@121.158,217.526 U1.3@121.158,220.066 121.158,239.268 114.938,245.488 104.14,245.488
NetC20_1: C20.1 R4.1 | length 92.8
  Top Layer w3: R4.1@17.68,268.986 22.318,268.986 C20.1@29.972,261.332
  Signal Layer 1 w3: R4.1@17.68,268.986 22.318,268.986 C20.1@29.972,261.332
  Signal Layer 2 w3: R4.1@17.68,268.986 22.318,268.986 C20.1@29.972,261.332
  Signal Layer 3 w3: R4.1@17.68,268.986 22.318,268.986 C20.1@29.972,261.332
  Signal Layer 4 w3: R4.1@17.68,268.986 22.318,268.986 C20.1@29.972,261.332
  Bottom Layer w3: R4.1@17.68,268.986 22.318,268.986 C20.1@29.972,261.332
NetC33_1: C33.1 R7.2 U5.2 | length 8.2
  Top Layer w0.508: R7.2@168.656,146.939 169.037,146.558 176.53,146.558 U5.2@176.657,146.431
NetC40_1: C40.1 R9.2 U7.2 | length 8
  Top Layer w0.508: R9.2@168.91,180.213 169.291,179.832 176.53,179.832 U7.2@176.657,179.705
NetC49_1: C49.1 Q1.3 R17.1 U5.3 | length 14.9
  Top Layer w0.508: Q1.3@168.218,139.827 167.919,139.827 166.878,140.868 166.878,143.383 168.148,144.653 168.656,144.653 171.196,144.653 171.831,145.288 176.53,145.288 U5.3@176.657,145.161
NetC50_1: C50.1 Q2.3 R18.1 U7.3 | length 14.9
  Top Layer w0.508: Q2.3@168.726,173.101 168.275,173.101 167.132,174.244 167.132,176.784 168.275,177.927 R18.1@168.91,177.927 C50.1@171.45,177.927 172.085,178.562 176.53,178.562 U7.3@176.657,178.435
NetC73_1: C73.1 R24.2 U10.2 | length 8.2
  Top Layer w0.508: R24.2@250.649,146.177 251.03,145.796 258.523,145.796 U10.2@258.65,145.669
NetC74_1: C74.1 R26.2 U11.2 | length 8
  Top Layer w0.508: R26.2@250.825,180.721 251.206,180.34 258.445,180.34 U11.2@258.572,180.213
NetC81_1: C81.1 Q3.3 R34.1 U10.3 | length 15.2
  Top Layer w0.508: Q3.3@250.465,138.811 250.063,138.811 248.92,139.954 248.92,142.494 250.317,143.891 R34.1@250.649,143.891 C81.1@253.189,143.891 253.824,144.526 258.523,144.526 U10.3@258.65,144.399
NetC82_1: C82.1 Q4.3 R35.1 U11.3 | length 14.8
  Top Layer w0.508: Q4.3@250.768,173.482 250.444,173.482 249.174,174.752 249.174,177.292 250.317,178.435 253.365,178.435 254,179.07 258.445,179.07 U11.3@258.572,178.943
NetC99_1: C99.1 R40.2 U14.2 | length 8.4
  Top Layer w0.508: R40.2@333.502,145.796 R40.2@332.994,146.304 335.788,146.304 336.296,145.796 U14.2@340.487,145.796
NetC100_1: C100.1 R42.2 U15.2 | length 8.1
  Top Layer w0.508: R42.2@332.994,180.086 333.502,179.578 340.73,179.578 U15.2@340.857,179.451
NetC107_1: C107.1 Q5.3 R50.1 U14.3 | length 15.7
  Top Layer w0.508: Q5.3@333.064,139.192 331.724,139.192 330.962,139.954 330.962,143.002 331.978,144.018 335.026,144.018 335.661,144.653 340.36,144.653 U14.3@340.487,144.526
NetC108_1: C108.1 Q6.3 R51.1 U15.3 | length 14.8
  Top Layer w0.508: Q6.3@332.81,172.974 332.308,172.974 331.343,173.939 331.343,176.53 332.613,177.8 332.994,177.8 333.502,178.308 340.73,178.308 U15.3@340.857,178.181
NetC110_1: C110.1 J5.12 R56.2 TP_IL1.1 | length 68.6
  Top Layer w0.381: J5.12@157.625,112.268 158.877,112.268 v2(159.258,112.649)
  Top Layer w0.508: C110.1@133.604,170.688 R56.2@135.636,170.688
  Signal Layer 2 w0.381: TP_IL1.1@135.128,167.386 159.258,143.256 v2(159.258,112.649)
NetC112_1: C112.1 J5.16 R62.2 TP_IL2.1 | length 64.5
  Top Layer w0.381: J5.16@157.625,109.728 159.004,109.728 162.306,113.03 v2(162.306,114.935) ; TP_IL2.1@158.242,167.132 TP_IL2.1@158.242,167.767
  Top Layer w0.508: C112.1@157.226,170.815 R62.2@159.004,170.815 ; R62.2@159.258,170.815 R62.2@159.512,170.815
  Signal Layer 2 w0.381: TP_IL2.1@158.242,167.132 162.306,163.068 v2(162.306,114.935)
NetC114_1: C114.1 J5.14 R68.2 TP_IL3.1 | length 67.5
  Top Layer w0.381: J5.14@157.625,110.998 159.258,110.998 160.782,112.522 v2(160.782,113.792)
  Top Layer w0.508: C114.1@145.415,170.766 R68.2@147.447,170.766
  Signal Layer 2 w0.381: TP_IL3.1@146.05,168.148 160.782,153.416 v2(160.782,113.792)
NetC115_1: C115.1 R74.2 R79.1 U20.1 | length 16.5
  Bottom Layer w0.508: U20.1@94.002,83.886 94.081,83.807 94.755,83.807 95.758,82.804 101.346,82.804 102.87,84.328 R79.1@102.87,85.344 102.87,88.519 102.743,88.392 R74.2@100.584,88.392
NetC115_2: C115.2 R74.1 R77.2 U20.4 | length 8.5
  Bottom Layer w0.381: U20.4@96.752,85.786 96.752,86.084 96.774,86.106 ; R74.1@98.552,88.875 R77.2@100.508,90.83
  Bottom Layer w0.508: 96.774,86.106 96.774,86.284 R74.1@98.171,87.681 ; R74.1@98.552,88.392 R74.1@98.552,88.875 ; R77.2@100.584,91.44 101.346,90.678 C115.2@102.997,90.678
NetC120_1: C120.1 R76.2 R77.1 | length 5.3
  Bottom Layer w0.508: C120.1@96.266,88.392 R76.2@96.266,91.44 R77.1@98.552,91.44
NetC120_2: C120.2 R80.2 R81.1 | length 6.2
  Bottom Layer w0.381: R80.2@89.916,90.957 R81.1@91.948,88.925
  Bottom Layer w0.508: R80.2@89.916,90.957 R80.2@89.916,91.44 ; R81.1@91.948,88.925 R81.1@91.948,88.392 C120.2@94.234,88.392
NetC122_2: C122.2 J5.5 R79.2 TP_VL1.1 | length 83.1
  Top Layer w0.508: v3(151.638,116.078) J5.5@153.565,116.078
  Signal Layer 2 w0.508: v2(105.664,86.868) 106.858,88.062 126.314,88.062 ; TP_VL1.1@133.096,78.232 133.096,81.28 126.314,88.062 ; v3(151.638,116.078) 141.224,105.664 141.224,93.726 135.56,88.062 126.314,88.062
  Bottom Layer w0.508: R79.2@104.902,85.344 104.902,88.138 C122.2@105.41,88.646
NetC123_1: C123.1 C124.1 L3.2 U21.3 U21.4 | length 7.3
  Top Layer w0.508: U21.4@133.152,67.252 U21.3@133.152,69.952
  Top Layer w1.016: L3.2@128.956,65.22 C123.1@128.956,67.506 C124.1@131.242,67.506
NetC125_1: C125.1 R81.2 R83.2 U20.3 | length 8.4
  Bottom Layer w0.381: R81.2@89.916,87.884 92.014,85.786 R83.2@92.39,85.786
  Bottom Layer w0.508: C125.1@87.63,88.392 R81.2@89.916,88.392 R81.2@89.916,87.884 ; R83.2@91.948,85.344 92.39,85.786 U20.3@94.002,85.786
NetC126_1: C126.1 R82.1 U19.3 | length 8.2
  Bottom Layer w0.508: U19.3@93.726,104.764 93.726,106.045 94.107,106.426 96.012,106.426 C126.1@97.536,104.902 ; C126.1@97.712,105.078 R82.1@100.076,105.078
NetC130_1: C130.1 R86.2 R91.1 U24.1 | length 16.6
  Bottom Layer w0.508: U24.1@70.634,83.886 71.716,82.804 77.788,82.804 79.629,84.645 R91.1@79.629,85.344 79.629,88.392 R86.2@79.756,88.519 77.47,88.519 C130.1@77.343,88.392
NetC130_2: C130.2 R86.1 R89.2 U24.4 | length 10.1
  Bottom Layer w0.381: C130.2@75.311,88.951 R89.2@77.343,90.983
  Bottom Layer w0.508: U24.4@73.384,85.786 73.384,86.033 75.311,87.96 C130.2@75.311,88.392 C130.2@75.311,88.951 ; R89.2@77.343,90.983 R89.2@77.343,91.44 78.232,90.551 R86.1@79.756,90.551
NetC138_1: C138.1 R88.2 R89.1 | length 5.3
  Bottom Layer w0.508: C138.1@73.025,88.392 R88.2@73.025,91.44 R89.1@75.311,91.44
NetC138_2: C138.2 R92.2 R93.1 | length 6.2
  Bottom Layer w0.381: R92.2@66.675,91.008 R93.1@68.707,88.976
  Bottom Layer w0.508: R92.2@66.675,91.008 R92.2@66.675,91.44 ; R93.1@68.707,88.976 R93.1@68.707,88.392 C138.2@70.993,88.392
NetC139_2: C139.2 J5.11 R91.2 TP_VL2.1 | length 96.7
  Top Layer w0.508: v3(151.638,112.268) J5.11@153.565,112.268
  Signal Layer 1 w0.508: TP_VL2.1@138.176,84.328 TP_VL2.1@138.43,84.074
  Signal Layer 4 w0.508: v2(82.55,86.868) 84.074,88.392 134.112,88.392 ; TP_VL2.1@138.176,84.328 134.112,88.392 ; v3(151.638,112.268) 147.574,108.204 147.574,98.552 137.414,88.392 134.112,88.392
  Bottom Layer w0.508: R91.2@81.661,85.344 81.661,87.884 C139.2@82.296,88.519
NetC140_1: C140.1 R93.2 R95.2 U24.3 | length 8.2
  Bottom Layer w0.381: R93.2@66.675,88.062 R95.2@69.05,85.687
  Bottom Layer w0.508: C140.1@64.262,88.392 R93.2@66.675,88.392 R93.2@66.675,88.062 ; R95.2@68.707,85.344 69.149,85.786 U24.3@70.634,85.786
NetC141_1: C141.1 R94.1 U23.3 | length 5.4
  Bottom Layer w0.508: U23.3@70.485,105.156 70.485,106.045 70.866,106.426 72.644,106.426 C141.1@74.168,104.902
NetC143_1: C143.1 R98.2 R103.1 U26.1 | length 16.3
  Bottom Layer w0.508: U26.1@117.116,83.886 118.198,82.804 124.206,82.804 125.984,84.582 R103.1@125.984,85.344 125.984,88.265 R98.2@126.111,88.392 C143.1@123.698,88.392
NetC143_2: C143.2 R98.1 R101.2 U26.4 | length 9.6
  Bottom Layer w0.381: C143.2@121.602,88.887 R101.2@123.698,90.983
  Bottom Layer w0.508: U26.4@119.866,85.786 119.866,86.033 121.666,87.833 C143.2@121.666,88.392 ; R101.2@123.698,90.983 R101.2@123.698,91.44 125.095,91.44 R98.1@126.111,90.424
NetC148_1: C148.1 R100.2 R101.1 | length 5.3
  Bottom Layer w0.508: C148.1@119.38,88.392 R100.2@119.38,91.44 R101.1@121.666,91.44
NetC148_2: C148.2 R104.2 R105.1 | length 6.2
  Bottom Layer w0.381: R104.2@113.03,90.856 R105.1@115.062,88.824
  Bottom Layer w0.508: R104.2@113.03,90.856 R104.2@113.03,91.44 ; R105.1@115.062,88.824 R105.1@115.062,88.392 C148.2@117.348,88.392
NetC149_2: C149.2 J5.9 R103.2 TP_VL3.1 | length 48.9
  Top Layer w0.508: v3(151.638,113.538) J5.9@153.565,113.538 ccw(c153.258,113.231) J5.9@153.258,113.665
  Signal Layer 2 w0.508: TP_VL3.1@133.35,84.328 142.24,93.218 142.24,105.156 150.622,113.538 v3(151.638,113.538)
  Bottom Layer w0.508: C149.2@128.524,88.392 128.016,87.884 R103.2@128.016,85.344 132.334,85.344 TP_VL3.1@133.35,84.328 TP_VL3.1@133.604,84.328
NetC150_1: C150.1 R105.2 R107.2 U26.3 | length 7.9
  Bottom Layer w0.381: R105.2@113.03,87.808 R107.2@114.935,85.903
  Bottom Layer w0.508: C150.1@110.617,88.392 R105.2@113.03,88.392 R105.2@113.03,87.808 ; R107.2@115.062,85.344 115.504,85.786 U26.3@117.116,85.786
NetC151_1: C151.1 R106.1 U25.3 | length 5.8
  Bottom Layer w0.508: U25.3@116.84,104.764 116.84,106.045 117.221,106.426 118.999,106.426 C151.1@120.523,104.902
NetC153_1: C153.1 R110.2 R115.1 U28.1 | length 10.9
  Top Layer w0.508: R115.1@226.416,36.07 226.67,36.324 R110.2@228.702,36.324 ; C153.1@228.702,38.864 R110.2@228.702,36.324 ; U28.1@228.768,31.139 228.768,31.968 229.718,32.918 229.718,34.849 228.702,35.865 R110.2@228.702,36.324
NetC153_2: C153.2 R110.1 R113.2 U28.4 | length 7.8
  Top Layer w0.508: U28.4@230.668,33.889 230.668,38.864 232.342,40.538 R113.2@232.766,40.538
NetC158_1: C158.1 R112.2 R113.1 | length 5
  Top Layer w0.508: C158.1@233.274,38.102 234.798,38.102 ; R113.1@234.798,40.538 234.798,38.102 ; R112.2@235.814,38.102 234.798,38.102
NetC158_2: C158.2 R116.2 R117.1 | length 5.7
  Top Layer w0.508: C158.2@233.02,36.07 233.02,34.188 235.456,31.752 R116.2@235.814,31.752
NetC159_2: C159.2 J5.17 R115.2 TP_VBUSPM_Fdbk1.1 | length 115.4
  Top Layer w0.508: J5.17@153.565,108.458 v2(154.94,108.458) ; TP_VBUSPM_Fdbk1.1@223.266,40.64 223.926,41.3 C159.2@226.162,41.3 226.416,41.046 R115.2@226.416,38.102
  Signal Layer 3 w0.508: v2(154.94,108.458) 157.988,108.458 167.132,99.314 167.132,80.264 191.008,56.388 207.518,56.388 TP_VBUSPM_Fdbk1.1@223.266,40.64
NetC160_1: C160.1 R117.2 R119.2 U28.3 | length 6.8
  Top Layer w0.508: U28.3@230.668,31.139 233.019,31.139 233.02,31.14 C160.1@233.02,29.466 ; R119.2@230.988,29.339 C160.1@233.782,29.339
NetC161_1: C161.1 R118.1 U27.3 | length 5.4
  Top Layer w0.508: U27.3@249.138,35.562 250.192,35.562 250.952,36.322 250.952,38.862 250.444,39.37
NetC162_1: C162.1 R122.2 R127.1 U30.1 | length 10.9
  Top Layer w0.508: R127.1@226.39,51.918 228.422,51.918 R122.2@228.676,52.172 ; C162.1@228.676,54.712 R122.2@228.676,52.172 ; U30.1@228.742,46.987 228.742,47.793 229.692,48.743 229.692,50.926 228.676,51.942 R122.2@228.676,52.172
NetC162_2: C162.2 R122.1 R125.2 U30.4 | length 9.7
  Top Layer w0.508: U30.4@230.642,49.737 230.642,56.22 232.689,58.268 R125.2@232.994,58.268
NetC167_1: C167.1 R124.2 R125.1 | length 5.1
  Top Layer w0.508: R125.1@232.994,56.236 C167.1@232.994,53.95 R124.2@235.788,53.95
NetC167_2: C167.2 R128.2 R129.1 | length 5.9
  Top Layer w0.508: C167.2@232.994,51.918 R129.1@232.994,49.632 233.375,49.632 235.407,47.6 R128.2@235.788,47.6
NetC168_2: C168.2 J5.20 R127.2 TP_VBUSMN_Fdbk1.1 | length 104.9
  Top Layer w0.508: J5.20@158.242,107.188 v2(161.29,107.188) ; R127.2@226.39,53.95 226.39,57.15 C168.2@226.06,57.15 224.282,57.15 ; 224.282,57.15 223.266,57.15 TP_VBUSMN_Fdbk1.1@223.012,57.404 224.028,57.404 224.282,57.15
  Signal Layer 3 w0.508: v2(161.29,107.188) 168.148,100.33 168.148,99.06 168.148,80.772 191.516,57.404 TP_VBUSMN_Fdbk1.1@223.012,57.404
NetC169_1: C169.1 R129.2 R131.2 U30.3 | length 6.8
  Top Layer w0.508: U30.3@230.642,46.987 232.972,46.987 232.994,46.965 232.994,45.314 ; R131.2@231.089,45.187 C169.1@233.883,45.187
NetC170_1: C170.1 R130.1 U29.3 | length 4.8
  Top Layer w0.508: U29.3@249.112,51.41 250.038,51.41 250.952,52.324 250.952,54.864
NetC206_1: C206.1 C207.1 C208.1 C230.1 S1.3 U35.1 | length 41.6
  Top Layer w3: 199.072,13.144 C230.1@213.908,13.144 ; C230.1@213.908,12.89 220.916,12.89 S1.3@225.17,8.636
  Bottom Layer w3: 200.216,13.144 C230.1@213.908,13.144
  other v1: 199.644,9.652 199.644,12.192 199.644,14.732 212.344,15.24 215.138,15.24 217.424,15.24 220.472,15.24
NetC211_1: C211.1 C212.1 C213.1 L9.2 U36.1 | length 2.8
  Top Layer w0.508: U36.1@205.994,39.37 208.661,39.37 L9.2@208.788,39.243
  other v2: 210.49,39.305 210.49,40.321
NetC227_1: C227.1 C231.1 L4.2 U22.1
NetC238_1: C238.1 C239.1 L6.2 U31.1 | length 9.4
  Top Layer w1.016: L6.2@233.401,24.359 236.926,24.359 U31.1@237.465,23.82
  Bottom Layer w1.016: U31.1@237.465,23.82 237.973,23.312 C239.1@237.973,21.438 C238.1@237.973,18.898
NetC244_1: C244.1 R67.2 U16.3 | length 5.6
  Top Layer w0.508: R67.2@134.112,180.086 134.112,179.578 135.956,177.734 U16.3@136.249,177.734 138.364,177.734 C244.1@138.43,177.8
NetC247_1: C247.1 R173.2 U17.3 | length 5.9
  Top Layer w0.508: R173.2@157.988,180.213 157.988,179.451 159.898,177.541 U17.3@160.23,177.541 162.174,177.541 C247.1@162.306,177.673
NetC250_1: C250.1 R176.2 U18.3 | length 5.7
  Top Layer w0.508: R176.2@146.177,180.291 R176.2@146.177,180.164 146.177,179.656 148.021,177.812 U18.3@148.314,177.812 150.483,177.812 C250.1@150.495,177.8
NetD1_2: D1.2 D4.1 Lboost1.2 Q7.2 Q9.2
  other v1: 208.534,217.932 210.312,217.932 212.09,217.932 208.534,219.71 210.312,219.71 212.09,219.71 208.534,221.488 210.312,221.488 212.09,221.488
NetD2_2: D2.2 D5.1 Lboost2.2 Q11.2 Q13.2
  other v1: 290.83,218.186 292.354,218.186 293.878,218.186 290.83,219.71 292.354,219.71 293.878,219.71 290.83,221.234 292.354,221.234 293.878,221.234
NetD3_2: D3.2 D6.1 Lboost3.2 Q15.2 Q17.2
  other v1: 372.872,217.932 374.65,217.932 376.428,217.932 372.872,219.71 374.65,219.71 376.428,219.71 372.872,221.488 374.65,221.488 376.428,221.488
NetD9_2: D9.2 R163.1 | length 2
  Top Layer w0.508: D9.2@248.412,9.432 R163.1@248.412,11.43
NetD10_2: D10.2 R164.1 | length 2
  Top Layer w1.016: D10.2@195.106,30.988 R164.1@197.104,30.988
NetD11_2: D11.2 R165.1 | length 2.3
  Top Layer w0.508: D11.2@208.788,44.357 R165.1@208.788,46.609
NetD12_2: D12.2 R166.1 | length 2
  Top Layer w1.016: R166.1@181.102,50.292 D12.2@183.1,50.292
NetD13_2: D13.2 R169.1 | length 2
  Top Layer w1: D13.2@99.602,205.486 R169.1@101.6,205.486
NetJ4_1: J4.1 R3.1 | length 3.9
  Top Layer w1.27: R3.1@167.132,87.63 170.688,87.63 J4.1@170.942,87.376
NetJ5_13: J5.13 U43.8 | length 111.2
  Top Layer w0.381: U43.8@83.027,181.06 83.027,180.498 v3(84.328,179.197) ; v3(139.192,142.494) 149.86,131.826 149.86,112.522 151.384,110.998 J5.13@153.565,110.998
  Signal Layer 2 w0.381: v3(84.328,179.197) 86.741,176.784 104.648,176.784 v3@138.938,142.494 ; v3@138.965,142.494 v3(139.192,142.494)
NetJ5_15: J5.15 U43.7 | length 112.4
  Top Layer w0.33: U43.7@82.356,181.06 82.356,179.899 v3(83.058,179.197)
  Top Layer w0.381: v3@83.046,179.197 v3(83.058,179.197) ; v3(139.192,141.224) 149.098,131.318 149.098,112.014 151.384,109.728 J5.15@153.162,109.728
  Signal Layer 2 w0.381: v3(83.058,179.197) 86.157,176.098 104.216,176.098 138.76,141.554 139.09,141.224 v3(139.192,141.224)
NetJ5_31: J5.31 U43.6 | length 122.4
  Top Layer w0.33: U43.6@81.706,181.06 81.711,181.06 81.711,180.16 81.703,180.153 81.703,179.605 81.711,179.598 81.711,179.197 v3(81.788,179.197) ; v3(139.192,139.954) 148.336,130.81 148.336,103.378 152.146,99.568 J5.31@153.162,99.568
  Signal Layer 2 w0.381: v3(81.788,179.197) 85.573,175.412 103.734,175.412 138.811,140.335 v3(139.192,139.954)
NetJ5_33: J5.33 U43.4 | length 124.1
  Top Layer w0.33: U43.4@80.406,181.06 80.406,179.467 ccw(c80.788,179.467) v3(80.518,179.197) ; v3@139.192,138.618 147.574,130.236 147.574,103.124 152.4,98.298 J5.33@153.162,98.298
  Signal Layer 1 w0.33: v3@139.192,138.618 v3(139.192,138.684)
  Signal Layer 1 w0.381: v3@80.391,179.324 v3(80.518,179.197)
  Signal Layer 2 w0.381: v3(80.518,179.197) 85.09,174.625 103.251,174.625 v3(139.192,138.684)
NetJ5_35: J5.35 U43.3 | length 125.8
  Top Layer w0.33: v3(79.248,179.197) cw(c79.555,179.197) 79.338,179.414 79.756,179.832 U43.3@79.756,181.06 ; 146.812,102.87 152.654,97.028 J5.35@153.162,97.028
  Top Layer w0.381: v3(139.192,137.414) 146.812,129.794 146.812,102.87
  Signal Layer 1 w0.381: v3@79.184,179.07 v3@79.375,179.07
  Signal Layer 2 w0.381: v3@79.375,179.07 84.506,173.939 102.667,173.939 v3(139.192,137.414)
NetJ5_37: J5.37 R9.1 R16.2 TP_G1.1 | length 105.4
  Top Layer w0.254: R9.1@168.656,182.499 R9.1@168.91,182.245
  Top Layer w0.381: J5.37@153.565,95.758 v3(155.194,95.758)
  Top Layer w0.508: R9.1@168.656,182.499 R16.2@168.656,184.785 168.656,186.182 172.212,189.738 TP_G1.1@174.244,189.738
  Signal Layer 2 w0.381: v3(155.194,95.758) 164.922,105.486 164.922,130.988 166.192,132.258 166.192,150.249 166.659,150.716 166.659,170.399 167.386,171.127 v2(167.386,183.388)
NetJ5_40: J5.40 R24.1 R31.2 TP_G4.1 | length 145.8
  Top Layer w0.381: J5.40@158.242,94.488 158.496,94.488 160.274,96.266 160.274,102.489 v3(174.625,116.84)
  Top Layer w0.508: R24.1@250.649,148.209 250.395,148.463 R31.2@250.395,150.749 250.395,151.335 254.762,155.702 TP_G4.1@256.032,155.702
  Signal Layer 2 w0.381: v3(174.625,116.84) 246.888,116.84 249.428,119.38 v2(249.428,149.352)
